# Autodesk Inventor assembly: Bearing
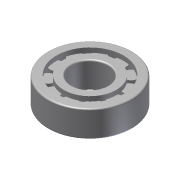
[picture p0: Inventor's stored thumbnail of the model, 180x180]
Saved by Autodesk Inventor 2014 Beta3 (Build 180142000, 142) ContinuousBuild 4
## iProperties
Created: 2010-12
Part Number: Bearing
Document SubType Name: Assembly
Designer: Beta-8540w
ClientObjectVersion: 1
Author: Beta-8540w
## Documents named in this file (2)
- C:\Inventor 2014 Essentials\Assemblies\Chapter 09\Design Accelerators\Bearing c0901.iam
- C:\Inventor 2014 Essentials\Content Center Files\en-US\SKF NJ\SKF NJNJ 202 EC.ipt
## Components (1 placed, 1 different names)
1. SKF NJ SKF NJNJ 202 EC:1
